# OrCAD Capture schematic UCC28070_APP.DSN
size Custom; title: UCC28070: Interleaving Continuous Mode PFC Controller; rev: 1.0; note: Datasheet: SLUS794C EVM Guide: SLUU312B
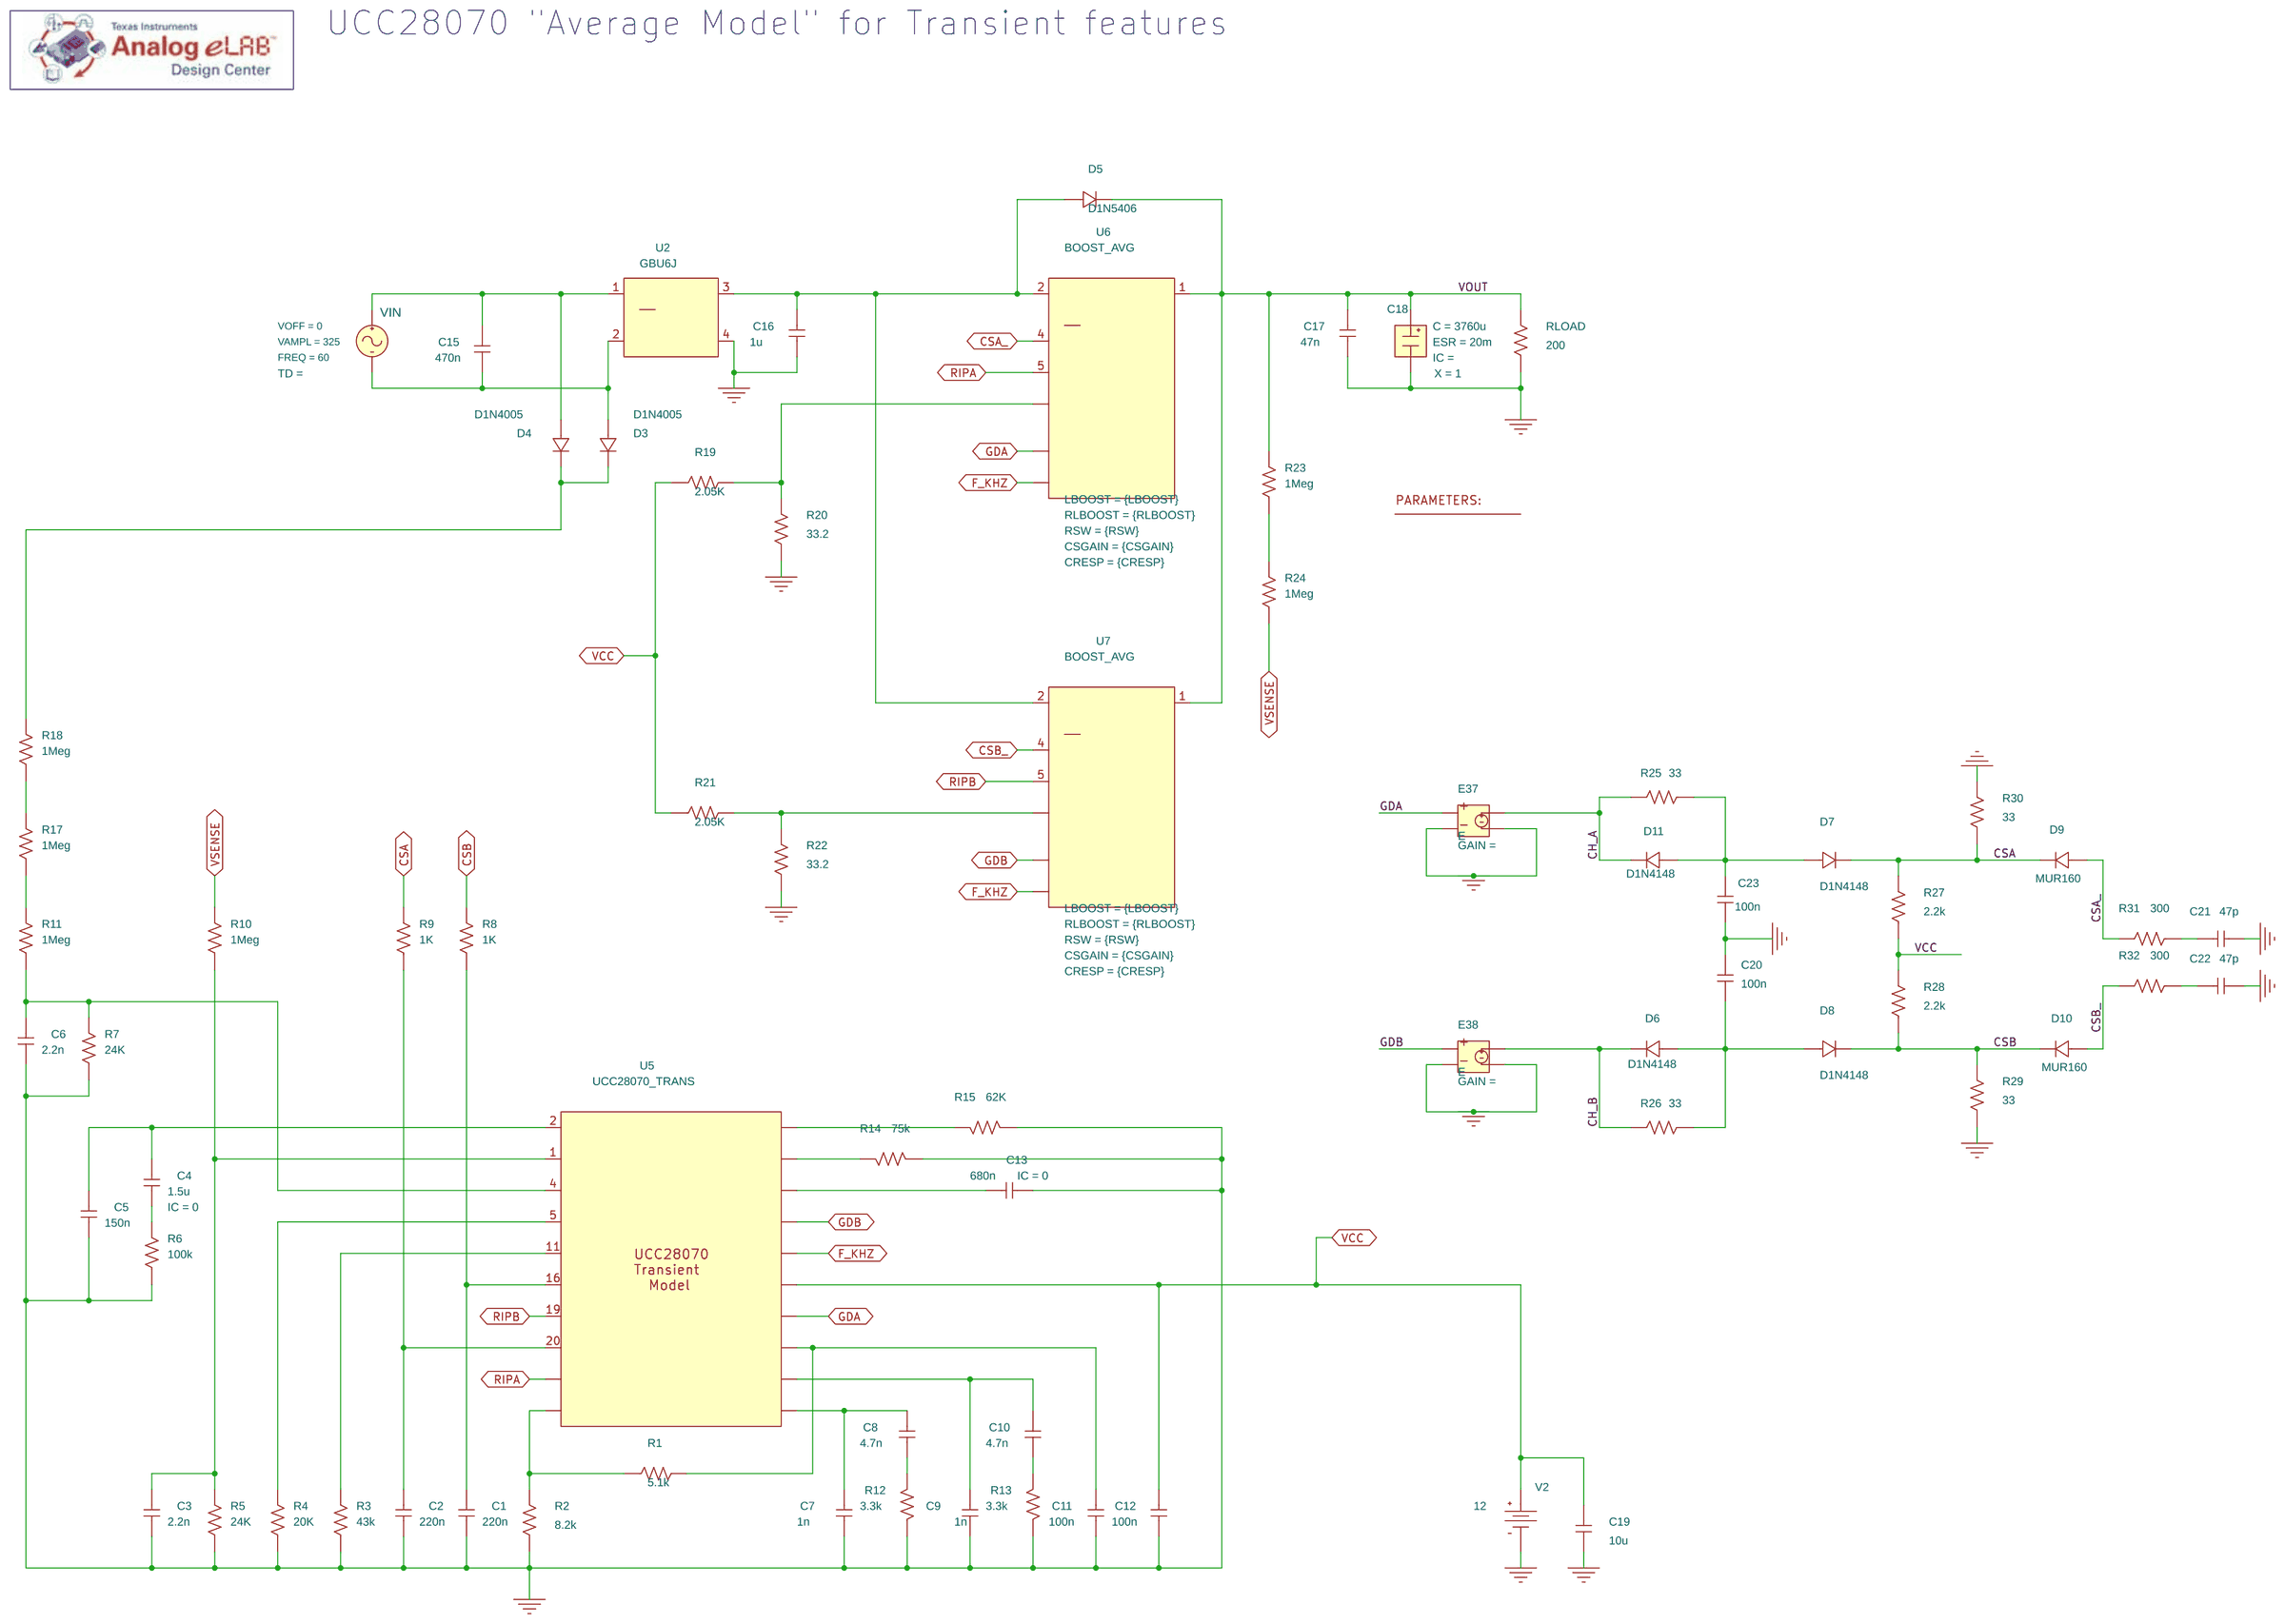
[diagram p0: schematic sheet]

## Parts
1  PARAM
C1  220n  [RAD/CK05]
C2  220n  [RAD/CK05]
C3  2.2n  [RAD/CK05]
C4  1.5u  [RAD/CK05]
C5  150n  [RAD/CK05]
C6  2.2n  [RAD/CK05]
C7  1n  [RAD/CK05]
C8  4.7n  [RAD/CK05]
C9  1n  [RAD/CK05]
C10  4.7n  [RAD/CK05]
C11  100n  [RAD/CK05]
C12  100n  [RAD/CK05]
C13  680n  [RAD/CK05]
C15  470n  [RAD/CK05]
C16  1u  [RAD/CK05]
C17  47n  [RAD/CK05]
C18  CESR
C19  10u  [RAD/CK05]
C20  100n  [RAD/CK05]
C21  47p  [RAD/CK05]
C22  47p  [RAD/CK05]
C23  100n  [RAD/CK05]
D3  D1N4005  [DO-41]
D4  D1N4005  [DO-41]
D5  D1N5406  [P26702]
D6  D1N4148  [DO-35]
D7  D1N4148  [DO-35]
D8  D1N4148  [DO-35]
D9  MUR160  [DO-41]
D10  MUR160  [DO-41]
D11  D1N4148  [DO-35]
E37  E
E38  E
R1  5.1k  [AX/RC05]
R2  8.2k  [AX/RC05]
R3  43k  [AX/RC05]
R4  20K  [AX/RC05]
R5  24K  [AX/RC05]
R6  100k  [AX/RC05]
R7  24K  [AX/RC05]
R8  1K  [AX/RC05]
R9  1K  [AX/RC05]
R10  1Meg  [AX/RC05]
R11  1Meg  [AX/RC05]
R12  3.3k  [AX/RC05]
R13  3.3k  [AX/RC05]
R14  75k  [AX/RC05]
R15  62K  [AX/RC05]
R17  1Meg  [AX/RC05]
R18  1Meg  [AX/RC05]
R19  2.05K  [AX/RC05]
R20  33.2  [AX/RC05]
R21  2.05K  [AX/RC05]
R22  33.2  [AX/RC05]
R23  1Meg  [AX/RC05]
R24  1Meg  [AX/RC05]
R25  33  [AX/RC05]
R26  33  [AX/RC05]
R27  2.2k  [AX/RC05]
R28  2.2k  [AX/RC05]
R29  33  [AX/RC05]
R30  33  [AX/RC05]
R31  300  [AX/RC05]
R32  300  [AX/RC05]
RLOAD  200  [AX/RC05]
U2  GBU6J
U5  UCC28070_TRANS
U6  BOOST_AVG
U7  BOOST_AVG
V2  VDC
VIN  VSIN

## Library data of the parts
1 = PARAM: CRESP: 220E-9; CSGAIN: 0.664; LBOOST: 18u; RLBOOST: 0.2; RSW: 0.52
C1-C3 C5-C12 C15-C17 C19-C23 = C
C4 C13 = C: IC: 0
C18 = CESR: C: 3760u; ESR: 20m; X: 1
D3 D4 = D1N4005
D5 = D1N5406
D6-D8 D11 = 1N4148
D9 D10 = MUR160
E37 E38 = E
R1-R15 R17-R32 RLOAD = R
U2 = GBU6J
U5 = UCC28070_TRANS
U6 = BOOST_AVG_1: CRESP: {CRESP}; CSGAIN: {CSGAIN}; LBOOST: {LBOOST}; RLBOOST: {RLBOOST}; RSW: {RSW}
U7 = BOOST_AVG: CRESP: {CRESP}; CSGAIN: {CSGAIN}; LBOOST: {LBOOST}; RLBOOST: {RLBOOST}; RSW: {RSW}
V2 = VDC: DC: 12
VIN = VSIN_0: FREQ: 60; VAMPL: 325; VOFF: 0

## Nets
VCC: C12.2 C19.2 R19.1 R21.1 R27.1 R28.2 U5.VCC V2.0(+)
0: C1.1 C2.1 C3.1 C5.1 C6.1 C7.1 C9.1 C11.1 C12.1 C13.2 C16.1 C17.1 C18.3(OUT) C19.1 C20.2 C21.1 C22.1 C23.1 E37.2 E37.4 E38.2 E38.4 R2.1 R3.1 R4.1 R5.1 R6.1 R7.1 R12.1 R13.1 R14.1 R15.1 R20.1 R22.1 R29.1 R30.2 RLOAD.1 U2.4(NEG) V2.1(-)
CH_A: D11.2 E37.3 R25.2
CH_B: D6.2 E38.3 R26.2
CSA: D7.2 D9.2 R9.2 R27.2 R30.1
CSA_: D9.1 R31.2 U6.4(CSX)
CSB: D8.2 D10.2 R8.2 R28.1 R29.2
CSB_: D10.1 R32.2 U7.4(CSX)
F_KHZ: U5.F_KHZ U6.K_KHZ U7.K_KHZ
GDA: E37.1 U5.GDA U6.GDX
GDB: E38.1 U5.GDB U7.GDX
RIPA: U5.IRIPA U6.5(IRIPX)
RIPB: U5.19(IRIPB) U7.5(IRIPX)
VOUT: C17.2 C18.1(IN) D5.1(2) R23.2 RLOAD.2 U6.1(VOUT) U7.1(VOUT)
VSENSE: R10.2 R24.1
N128440: C16.2 D5.2(1) U2.3(POS) U6.2(VIN) U7.2(VIN)
N128454: C7.2 C8.2 U5.CAOB
N128464: C8.1 R12.2
N128470: C15.2 D4.1 U2.1(AC1) VIN.1(+)
N128486: C15.1 D3.1 U2.2(AC2) VIN.2(-)
N128542: C9.2 C10.2 U5.CAOA
N128558: C10.1 R13.2
N128602: C11.2 R1.2 U5.VREF
N128632: R17.2 R18.1
N128708: R19.2 R20.2 U6.CSOFFX
N128746: R21.2 R22.2 U7.CSOFFX
N128754: D3.2 D4.2 R18.2
N128818: R1.1 R2.2 U5.PKLIMIT
N128870: C1.2 R8.1 U5.16(CSB)
N128878: C2.2 R9.1 U5.20(CSA)
N128902: R23.1 R24.2
N128960: R3.2 U5.11(RSYNTH)
N128982: R4.2 U5.5(IMO)
N129008: C3.2 R5.2 R10.1 U5.1(VSENSE)
N129058: R14.2 U5.RT
N129064: C13.1 U5.SS
N129074: C4.2 C5.2 U5.2(VAO)
N129100: C4.1 R6.2
N129142: R15.2 U5.DMAX
N129258: C6.2 R7.2 R11.1 U5.4(VINAC)
N130640: R11.2 R17.1
N14215075: C23.2 D7.1 D11.1 R25.1
N14215083: C20.1 D6.1 D8.1 R26.1
N14215201: C22.2 R32.1
N14215205: C21.2 R31.1

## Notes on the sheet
- UCC28070 "Average Model" for Transient features
